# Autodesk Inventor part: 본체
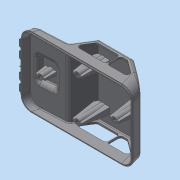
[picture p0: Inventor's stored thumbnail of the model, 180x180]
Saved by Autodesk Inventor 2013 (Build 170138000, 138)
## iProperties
Created: 2015-05
Part Number: 본체
Material: 일반
Document SubType Name: Modeling
Designer: Administrator
Density: 1 g/cm^3
Author: Administrator
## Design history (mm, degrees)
sketch "스케치1"
  geometry: L1 (0, 0)-(122, 0); L2 (0, 0)-(1.608, 6); L3 (55.441, 31)-(92, 31); L4 (54.497, 31)-(55.441, 31); L5 (42, 11)-(54.497, 31); L6 (122, 0)-(122, 11); L7 (42, 11)-(2.391, 8.924); L8 (2.391, 8.924)-(1.474, 5.5); L9 (122, 0)-(119.053, 11); L10 (119.053, 11)-(92, 31); 1 further point
  constraints: 20 end point, 2 horizontal, 2 point on line, 1 coincident, 1 parallel, 1 perpendicular
  dimensions: "d0" = 122 distance of L1.start L1.end; "d1" = 105 deg angle of L2 L1; "d3" = 5 vertical distance of L5.start L2.end; "d9" = 6 vertical distance of point (0, 0) L2.end; "d19" = 3 deg angle of L1 L7; "d20" = 42 horizontal distance of L5.start point (0, 0); "d21" = 125 deg angle of L5 L7; "d42" = 31 distance between parallel lines of L1 L3; "d43" = 105 deg angle of L1 L9; "d44" = 20 vertical distance of L9.end L3.end; "d45" = 30 horizontal distance of L6.end L3.end
extrude "돌출1" new body sketch "스케치1" stored distance "d11" = 76; taper "d12" = 0 deg
sketch "스케치3"
  geometry: L1 (8.145, 51)-(28.145, 51); L2 (28.145, 51)-(28.145, 25); L3 (28.145, 25)-(8.145, 25); L4 (8.145, 25)-(8.145, 51); L5 (-2.855, 0)-(-2.855, 76) reference; 2 further points
  constraints: 8 end point, 2 parallel, 1 horizontal, 1 horizontal alignment, 1 midpoint, 1 perpendicular
  dimensions: "d22" = 20 distance of L1.start L1.end; "d24" = 26 distance of L3.end L1.start; "d25" = 11 distance from line of L1.start L5
extrude "돌출3" join sketch "스케치3" distance "d26" = 5; taper "d27" = 0 deg
fillet "모깎기1" dims "d28" = 12
fillet "모깎기2" dims "d30" = 3
fillet "모깎기3" dims "d31" = 3
fillet "모깎기4" dims "d32" = 3, "d33" = 3
fillet "모깎기6" dims "d46" = 3, "d47" = 12
sketch "스케치7"
  geometry: L1 (104.807, 17.801)-(109.577, 0) reference; L2 (45.372, 10.735)-(56.16, 28) reference; L3 (12.423, 0)-(109.577, 0) reference; L4 (47.896, 11)-(57.269, 26); L5 (90.352, 26)-(105.638, 14.699); L6 (57.269, 26)-(81.896, 26); L7 (82.642, 26)-(90.352, 26); L8 (53.616, 29.59)-(42.828, 12.324) reference; L9 (91.011, 31)-(56.16, 31) reference; L10 (106.59, 20.213)-(92.795, 30.412) reference; L11 (12.423, 0)-(0, 0) reference; L12 (122, 0)-(109.577, 0) reference; L13 (47.896, 11)-(81.896, 11); L14 (81.896, 26)-(81.896, 11); L15 (82.642, 26)-(82.642, 11); L16 (82.642, 11)-(103.794, 11); L17 (103.794, 11)-(110.642, 11); L18 (105.638, 14.699)-(110.642, 11)
  constraints: 21 end point, 7 parallel, 3 collinear, 2 perpendicular, 1 point on line
  dimensions: "d48" = 5 distance between parallel lines of L4 L8; "d49" = 5 distance between parallel lines of L7 L9; "d54" = 5 distance between parallel lines of L10 L5; "d55" = 15 vertical distance of L4.start L4.end; "d57" = 34 distance of L13.end L4.start; "d58" = 28 distance of L17.end L15.end
feature "쉘1" dims "d29" = 2
extrude "돌출4" cut sketch "스케치7" distance "d59" = 10; taper "d60" = 0 deg
fillet "모깎기7" dims "d61" = 3
fillet "모깎기8" dims "d62" = 3
sketch "스케치9"
  geometry: L1 (12.423, 64)-(109.577, 64) reference; L2 (0, 52)-(0, 0) reference; L3 (109.577, -12)-(12.423, -12) reference; L4 (122, 0)-(122, 52) reference; L5 (121, 52)-(121, 0); L6 (109.577, -11)-(12.423, -11); L7 (1, 0)-(1, 52); L8 (12.423, 63)-(109.577, 63); 5 further points; 4 other entities
  constraints: 8 end point, 7 parallel, 16 other
  dimensions: "d67" = 1 distance between parallel lines of L4 L5
extrude "돌출6" cut sketch "스케치9" distance "d68" = 1; taper "d69" = 0 deg
node "작업 평면1"
sketch "스케치10"
  geometry: A1 r 4 centre (-1, -21) between (-1, -17) and (-1, -25); A2 r 4 centre (-1, -10) between (-1, -6) and (-1, -14); A3 r 4 centre (-1, 10) between (-1, 14) and (-1, 6); A4 r 4 centre (-1, 21) between (-1, 25) and (-1, 17); 3 further points
  constraints: 8 point on circle, 4 centre point, 3 vertical alignment, 9 other
  dimensions: "d71" = 8 diameter of A1; "d72" = 8 diameter of A2; "d73" = 8 diameter of A3; "d74" = 8 diameter of A4; "d75" = 1 horizontal distance of point (0, 0) A2.centre; "d76" = 11 distance of A2.centre A1.centre; "d77" = 11 distance of A4.centre A3.centre; "d78" = 20 distance of A3.centre A2.centre; "d79" = 10 vertical distance of point (0, 0) A2.centre
extrude "돌출7" join sketch "스케치10" stored distance "d80" = 1; taper "d81" = 0 deg
chamfer "모따기1" distance "d82" = 1; stored, may be unused: second distance "d83" = 2, angle "d84" = 45 deg
chamfer "모따기2" distance "d85" = 1; stored, may be unused: second distance "d86" = 2, angle "d87" = 45 deg
sketch "스케치11"
  geometry: L1 (65.572, 9)-(65.572, 61) reference; 2 further points
  constraints: 1 horizontal alignment, 1 other
  dimensions: "d88" = 50 distance from line of L1 point (15.572, 35)
feature "엠보싱1" sketch "스케치11" dims "d0" = 122, "d1" = 105 deg, "d3" = 5, "d9" = 6, "d19" = 3 deg, "d20" = 42, "d21" = 125 deg, "d42" = 31, "d43" = 105 deg, "d44" = 20, "d45" = 30, "d89" = 0.5, "d90" = 0
node "작업 평면2"
sketch "스케치13"
  geometry: L1 (121.732, 26)-(121.732, -26) reference; C1 r 3 at (100.732, 0); C2 r 3 at (60.732, -22); C3 r 3 at (20.732, 0); 1 further point
  constraints: 3 centre point, 2 horizontal alignment
  dimensions: "d92" = 6 diameter of C1; "d93" = 6 diameter of C2; "d94" = 6 diameter of C3; "d95" = 21 distance from line of C1.centre L1; "d96" = 40 horizontal distance of C2.centre C1.centre; "d97" = 40 horizontal distance of C3.centre C2.centre; "d98" = 22 vertical distance of C2.centre point (0, 0)
extrude "돌출8" join sketch "스케치13" stored distance "d99" = 2; taper "d100" = 2 deg
sketch "스케치16"
  geometry: 1 further point
sketch "스케치17"
  geometry: L1 (-5, 1)-(5, 1); L2 (5, 1)-(5, -1); L3 (5, -1)-(-5, -1); L4 (-5, -1)-(-5, 1); L5 (35, 23)-(45, 23); L6 (45, 23)-(45, 21); L7 (45, 21)-(35, 21); L8 (35, 21)-(35, 23); L9 (-35, 23)-(-45, 23); L10 (-45, 23)-(-45, 21); L11 (-45, 21)-(-35, 21); L12 (-35, 21)-(-35, 23); C1 r 3 at (0, 0) reference; C2 r 3 at (-40, 22) reference; C3 r 3 at (40, 22) reference; 7 further points
  constraints: 24 end point, 8 parallel, 6 midpoint, 3 horizontal, 3 horizontal alignment, 3 perpendicular, 3 vertical alignment
  dimensions: "d104" = 2 distance of L1.end L2.end; "d106" = 10 distance of L1.start L1.end; "d107" = 10 distance of L5.start L5.end; "d108" = 10 distance of L9.start L9.end
extrude "돌출10" join sketch "스케치17" stored distance "d109" = 2; taper "d110" = 5 deg
sketch "스케치19"
  geometry: L1 (65.732, 23)-(63.56, 23) reference; L2 (57.904, 23)-(55.732, 23) reference; L3 (55.732, 23)-(55.732, 21) reference; L4 (55.732, 21)-(57.904, 21) reference; L5 (63.56, 21)-(65.732, 21) reference; L6 (65.732, 21)-(65.732, 23) reference; L7 (105.732, -1)-(103.56, -1) reference; L8 (105.732, 1)-(105.732, -1) reference; L9 (103.56, 1)-(105.732, 1) reference; L10 (95.732, 1)-(97.904, 1) reference; L11 (95.732, -1)-(95.732, 1) reference; L12 (97.904, -1)-(95.732, -1) reference; L13 (65.732, -23)-(63.56, -23) reference; L14 (65.732, -21)-(65.732, -23) reference; L15 (63.56, -21)-(65.732, -21) reference; L16 (55.732, -21)-(57.904, -21) reference; L17 (55.732, -23)-(55.732, -21) reference; L18 (57.904, -23)-(55.732, -23) reference; A1 r 3 centre (20.732, 0) between (17.904, -1) and (23.56, -1) reference; A2 r 3 centre (60.732, 22) between (63.56, 23) and (57.904, 23) reference; A3 r 3 centre (60.732, 22) between (57.904, 21) and (63.56, 21) reference; A4 r 3 centre (100.732, 0) between (97.904, -1) and (103.56, -1) reference; A5 r 3 centre (100.732, 0) between (103.56, 1) and (97.904, 1) reference; A6 r 3 centre (60.732, -22) between (57.904, -23) and (63.56, -23) reference; A7 r 3 centre (60.732, -22) between (63.56, -21) and (57.904, -21) reference; 1 further point
hole "구멍1" sketch "스케치19" at (60.732, 22), (100.732, 0), (60.732, -22), (20.732, 0) diameter "d111" = 3.242; stored, may be unused: countersink angle "d115" = 90 deg, drill point angle "d117" = 118 deg; dims "d112" = 9, "d113" = 4, "d114" = 2, "d116" = 11
node "솔리드1"
mirror "대칭1"
mirror "대칭2"
node "투영된 루프3"
node "투영된 루프4"
node "투영된 루프5"
node "투영된 루프6"
node "투영된 루프7"
other parameters: "d70" = -2, "d91" = 1
